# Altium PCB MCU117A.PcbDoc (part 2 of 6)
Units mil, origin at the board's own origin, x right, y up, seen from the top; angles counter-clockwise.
Board outline 2300 x 6749.64 mil, 6 copper layers (Top Signal, GND, Middle Signal, PWR, GND2, Bottom Signal), stack 61.64 mil thick; 424 components, 343 nets, 1563 pads, 921 vias.
Unrouted connection lines stored in the file: 4.
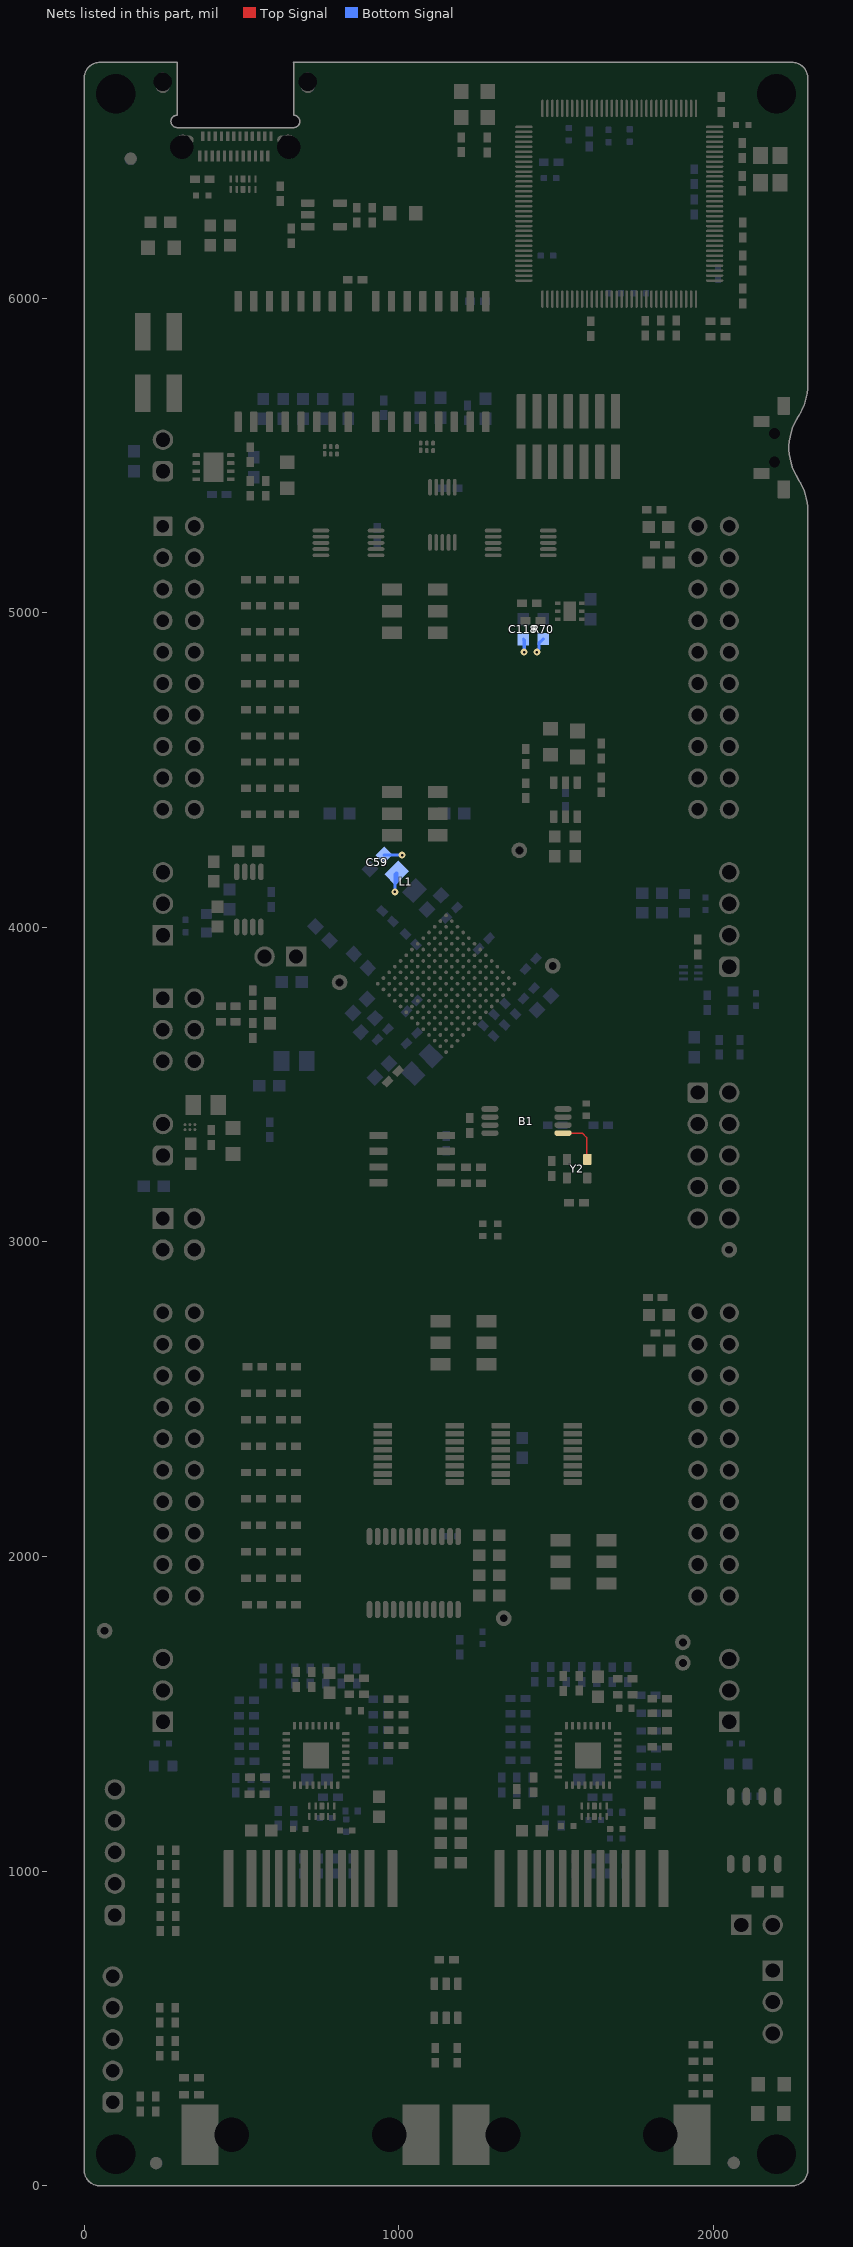
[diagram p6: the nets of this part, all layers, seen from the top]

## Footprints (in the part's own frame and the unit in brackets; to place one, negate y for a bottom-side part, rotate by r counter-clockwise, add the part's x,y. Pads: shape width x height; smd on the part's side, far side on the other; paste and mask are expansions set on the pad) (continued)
DW0016B_HV [mm] "SOIC-16, HV/isolation option"
  rrect17% 1.65x0.6 smd: 1(-4.875,4.445) 2(-4.875,3.175) 3(-4.875,1.905) 4(-4.875,0.635) 5(-4.875,-0.635) 6(-4.875,-1.905) 7(-4.875,-3.175) 8(-4.875,-4.445) 9(4.875,-4.445) 10(4.875,-3.175) 11(4.875,-1.905) 12(4.875,-0.635) 13(4.875,0.635) 14(4.875,1.905) 15(4.875,3.175) 16(4.875,4.445)
  body extent -5.17,-5.15 5.17,5.15, height 2.59
EtherCAT_label [mil] "ETHERCAT_LABEL"
FCC_disclaimer [mil]
Fiducial10-20 [mm]
  round 1 smd mask+0.5: 1(0,0)
  Top Signal keep-out circle w1.178: c0,0 r0.5
FP-61300421121_HDR4-MFG [mm]
  rrect6% 1.7x1.7 hole 1.1: 1(-1.27,-1.27)
  round 1.7 hole 1.1: 2(-1.27,1.27) 3(1.27,-1.27) 4(1.27,1.27)
  silkscreen extent -2.69,-3.22 2.69,2.62, body extent -2.79,-2.72 2.79,2.72, height 0.25
FP-885012005053_0402-MFG [mm]
  rrect20% 0.5x0.5 smd paste+0 mask+0: 1(-0.5,0) 2(0.5,0)
  silkscreen extent -0.53,-0.63 0.53,0.63, body extent -0.5,-0.25 0.5,0.25, height 0.55
FP-885012205018_0402-MFG [mm]
  rrect20% 0.5x0.5 smd paste+0 mask+0: 1(-0.5,0) 2(0.5,0)
  silkscreen extent -0.5,-0.63 0.5,0.63, body extent -0.5,-0.25 0.5,0.25, height 0.55
FP-885012205050_0402-MFG [mm]
  rrect20% 0.5x0.5 smd paste+0 mask+0: 1(-0.5,0) 2(0.5,0)
  silkscreen extent -0.53,-0.63 0.53,0.63, body extent -0.85,-0.38 0.85,0.38, height 0.25
FP-885012205064_0402-MFG [mm]
  rrect20% 0.5x0.5 smd paste+0 mask+0: 1(-0.5,0) 2(0.5,0)
  silkscreen extent -0.53,-0.63 0.53,0.63, body extent -0.85,-0.38 0.85,0.38, height 0.25
FP-CC0603KRX5R6BB106_0603-MFG [mm]
  rrect13% 0.8x0.9 smd paste+0 mask+0: 1(-0.75,0) 2(0.75,0)
  silkscreen extent -0.85,-0.87 0.85,0.87, body extent -0.8,-0.4 0.8,0.4, height 1
FP-FTSH-107-01-F-DV-K_HDR14-MFG [mm]
  rrect14% 0.74x2.79 smd paste+0 mask+0: 1(-3.81,-2.035) 2(-3.81,2.035) 3(-2.54,-2.035) 4(-2.54,2.035) 5(-1.27,-2.035) 6(-1.27,2.035) 7(0,-2.035) 8(0,2.035) 9(1.27,-2.035) 10(1.27,2.035) 11(2.54,-2.035) 12(2.54,2.035) 13(3.81,-2.035) 14(3.81,2.035)
  silkscreen extent -4.51,-4.11 4.51,0.27, body extent -4.61,-3.53 4.61,3.53, height 0.25
FP-MUP-U22001_CONN_USB_8MM94_8MM0-MFG [mm]
  rrect100% 0.6x1.9 hole 1.9 slot 0.6 at 0 deg: 1(-4.32,3.35) 2(4.32,3.35)
  round 1.207 smd: 1(-4.25,2.92) 2(4.25,2.92)
  round 1.207 smd far side: 1(-4.25,2.92) 2(4.25,2.92)
  rrect100% 1.25x0.7 hole 0.7 slot 1.25 at 0 deg: 1(-3.995,2.75) 2(3.995,2.75)
  rrect100% 0.7x1.5 hole 1.5 slot 0.7 at 0 deg: 3(-5.85,-1.95) 4(5.85,-1.95)
  round 1.17 smd far side: 3(-5.85,-1.625) 4(5.85,-1.625)
  round 1.17 smd: 3(-5.85,-1.625) 4(5.85,-1.625)
  rrect37% 0.27x0.9 smd: A1(-2.625,4.05) A2(-2.125,4.05) A3(-1.625,4.05) A4(-1.125,4.05) A5(-0.625,4.05) A6(-0.125,4.05) A7(0.375,4.05) A8(0.875,4.05) A9(1.375,4.05) A10(1.875,4.05) A11(2.375,4.05) A12(2.875,4.05)
  rrect37% 0.27x0.8 smd: B1(2.625,2.45) B2(2.125,2.45) B3(1.625,2.45) B4(1.125,2.45) B5(0.625,2.45) B6(0.125,2.45) B7(-0.375,2.45) B8(-0.875,2.45) B9(-1.375,2.45) B10(-1.875,2.45) B11(-2.375,2.45) B12(-2.875,2.45)
  Top Signal region: -6.5,-2.349 -6.5,-2.472 -6.411,-2.701 -6.244,-2.882 -6.023,-2.99 -5.9,-2.999 -5.9,-2.999 -5.833,-3.004 -5.699,-2.987 -5.572,-2.942 -5.457,-2.873 -5.358,-2.781 -5.281,-2.672 -5.227,-2.548 -5.2,-2.416 -5.2,-2.349 -5.2,-2.349 -5.2,-0.749 -5.2,-0.65 -5.276,-0.466 -5.417,-0.325 -5.601,-0.249 -5.7,-0.249 -5.7,-0.249 -6,-0.249 -6.099,-0.249 -6.283,-0.325 -6.424,-0.466 -6.5,-0.65 -6.5,-0.749 -6.5,-0.749
  Top Signal region: 6.5,-2.349 6.5,-2.472 6.411,-2.701 6.244,-2.882 6.023,-2.99 5.9,-2.999 5.833,-3.004 5.699,-2.987 5.572,-2.942 5.457,-2.873 5.358,-2.781 5.281,-2.672 5.227,-2.548 5.2,-2.416 5.2,-2.349 5.2,-2.349 5.2,-0.749 5.2,-0.65 5.276,-0.466 5.417,-0.325 5.601,-0.249 5.7,-0.249 5.7,-0.249 6,-0.249 6.099,-0.249 6.283,-0.325 6.424,-0.466 6.5,-0.65 6.5,-0.749 6.5,-0.749
  Top Signal region: -3.72,3.35 -3.72,4.05 -3.72,4.169 -3.811,4.39 -3.98,4.559 -4.201,4.65 -4.32,4.65 -4.439,4.65 -4.66,4.559 -4.829,4.39 -4.92,4.169 -4.92,4.05 -4.92,4.05 -4.92,2.85 -4.92,2.731 -4.829,2.51 -4.66,2.341 -4.439,2.25 -4.32,2.25 -4.32,2.25 -3.82,2.25 -3.711,2.25 -3.508,2.334 -3.354,2.488 -3.27,2.691 -3.27,2.8 -3.268,2.898 -3.332,3.082 -3.456,3.233 -3.624,3.332 -3.72,3.35
  Top Signal region: 3.72,3.35 3.72,4.05 3.72,4.169 3.811,4.39 3.98,4.559 4.201,4.65 4.32,4.65 4.439,4.65 4.66,4.559 4.829,4.39 4.92,4.169 4.92,4.05 4.92,4.05 4.92,2.85 4.92,2.731 4.829,2.51 4.66,2.341 4.439,2.25 4.32,2.25 4.32,2.25 3.82,2.25 3.711,2.25 3.508,2.334 3.354,2.488 3.27,2.691 3.27,2.8 3.268,2.898 3.332,3.082 3.456,3.233 3.624,3.332 3.72,3.35 3.72,3.35
  Bottom Signal region: -6.5,-2.349 -6.5,-2.472 -6.411,-2.701 -6.244,-2.882 -6.023,-2.99 -5.9,-2.999 -5.833,-3.004 -5.699,-2.987 -5.572,-2.942 -5.457,-2.873 -5.358,-2.781 -5.281,-2.672 -5.227,-2.548 -5.2,-2.416 -5.2,-2.349 -5.2,-2.349 -5.2,-0.749 -5.2,-0.65 -5.276,-0.466 -5.417,-0.325 -5.601,-0.249 -5.7,-0.249 -5.7,-0.249 -6,-0.249 -6.099,-0.249 -6.283,-0.325 -6.424,-0.466 -6.5,-0.65 -6.5,-0.749 -6.5,-0.749
  Bottom Signal region: 6.5,-2.349 6.5,-2.472 6.411,-2.701 6.244,-2.882 6.023,-2.99 5.9,-2.999 5.833,-3.004 5.699,-2.987 5.572,-2.942 5.457,-2.873 5.358,-2.781 5.281,-2.672 5.227,-2.548 5.2,-2.416 5.2,-2.349 5.2,-2.349 5.2,-0.749 5.2,-0.65 5.276,-0.466 5.417,-0.325 5.601,-0.249 5.7,-0.249 5.7,-0.249 6,-0.249 6.099,-0.249 6.283,-0.325 6.424,-0.466 6.5,-0.65 6.5,-0.749 6.5,-0.749
  Bottom Signal region: -3.72,3.35 -3.72,4.05 -3.72,4.169 -3.811,4.39 -3.98,4.559 -4.201,4.65 -4.32,4.65 -4.439,4.65 -4.66,4.559 -4.829,4.39 -4.92,4.169 -4.92,4.05 -4.92,4.05 -4.92,2.85 -4.92,2.731 -4.829,2.51 -4.66,2.341 -4.439,2.25 -4.32,2.25 -4.32,2.25 -3.82,2.25 -3.711,2.25 -3.508,2.334 -3.354,2.488 -3.27,2.691 -3.27,2.8 -3.268,2.898 -3.332,3.082 -3.456,3.233 -3.624,3.332 -3.72,3.35
  Bottom Signal region: 3.72,3.35 3.72,4.05 3.72,4.169 3.811,4.39 3.98,4.559 4.201,4.65 4.32,4.65 4.439,4.65 4.66,4.559 4.829,4.39 4.92,4.169 4.92,4.05 4.92,4.05 4.92,2.85 4.92,2.731 4.829,2.51 4.66,2.341 4.439,2.25 4.32,2.25 4.32,2.25 3.82,2.25 3.711,2.25 3.508,2.334 3.354,2.488 3.27,2.691 3.27,2.8 3.268,2.898 3.332,3.082 3.456,3.233 3.624,3.332 3.72,3.35
  Keep-Out Layer lines w0.2: 4.7,-3.5 4.7,0.75 ccw(c4.7,1.25) 5.2,1.25 ccw(c4.7,1.25) 4.7,1.75 -4.7,1.75 ccw(c-4.7,1.25) -5.2,1.25 ccw(c-4.7,1.25) -4.7,0.75 -4.7,-3.5
  silkscreen extent -6,0.13 6,5.17, body extent -6.6,-4.23 6.6,4.75, height 0.25
"FP-RMCF0402ZT0R00_0402 (1005 metric)-0" [mm]
  rrect20% 0.5x0.6 smd paste+0 mask+0: 1(-0.5,0) 2(0.5,0)
  body extent -0.5,-0.25 0.5,0.25, height 0.35
LED_LTST-C171 [mm] "LITE-ON"
  rect 1.2x1.2 smd: 1(-1.05,0) 2(1.05,0)
  silkscreen extent -1.6,-1 2.2,1, body extent -1.05,-0.67 1.05,0.67, height 0.8
LTST-C170TBKT_Blue [mm] "LITE-ON"
  rect 1.2x1.2 smd: 1(-1.05,0) 2(1.05,0)
  silkscreen extent -1.6,-1 2.2,1, body extent -1.05,-0.67 1.05,0.67, height 1.2
NDK_NX3225GA [mm] "NDK"
  rect 1.2x1.4 smd: 1(-0.8,1.1) 2(-0.8,-1.1) 3(0.8,-1.1) 4(0.8,1.1)
  silkscreen extent -1.9,-0.1 1.4,2, body extent -1.3,-1.65 1.3,1.65, height 0.9
NMR0169A-MFG [mm]
  round 0.3 smd paste+0 mask+0: A1(-3.9,3.9) A2(-3.25,3.9) A3(-2.6,3.9) A4(-1.95,3.9) A5(-1.3,3.9) A6(-0.65,3.9) A7(0,3.9) A8(0.65,3.9) A9(1.3,3.9) A10(1.95,3.9) A11(2.6,3.9) A12(3.25,3.9) A13(3.9,3.9) B1(-3.9,3.25) B2(-3.25,3.25) B3(-2.6,3.25) B4(-1.95,3.25) B5(-1.3,3.25) B6(-0.65,3.25) B7(0,3.25) B8(0.65,3.25) B9(1.3,3.25) B10(1.95,3.25) B11(2.6,3.25) B12(3.25,3.25) B13(3.9,3.25) C1(-3.9,2.6) C2(-3.25,2.6) C3(-2.6,2.6) C4(-1.95,2.6) C5(-1.3,2.6) C6(-0.65,2.6) C7(0,2.6) C8(0.65,2.6) C9(1.3,2.6) C10(1.95,2.6) C11(2.6,2.6) C12(3.25,2.6) C13(3.9,2.6) D1(-3.9,1.95) D2(-3.25,1.95) D3(-2.6,1.95) D4(-1.95,1.95) D5(-1.3,1.95) D6(-0.65,1.95) D7(0,1.95) D8(0.65,1.95) D9(1.3,1.95) D10(1.95,1.95) D11(2.6,1.95) D12(3.25,1.95) D13(3.9,1.95) E1(-3.9,1.3) E2(-3.25,1.3) E3(-2.6,1.3) E4(-1.95,1.3) E5(-1.3,1.3) E6(-0.65,1.3) E7(0,1.3) E8(0.65,1.3) E9(1.3,1.3) E10(1.95,1.3) E11(2.6,1.3) E12(3.25,1.3) E13(3.9,1.3) F1(-3.9,0.65) F2(-3.25,0.65) F3(-2.6,0.65) F4(-1.95,0.65) F5(-1.3,0.65) F6(-0.65,0.65) F7(0,0.65) F8(0.65,0.65) F9(1.3,0.65) F10(1.95,0.65) F11(2.6,0.65) F12(3.25,0.65) F13(3.9,0.65) G1(-3.9,0) G2(-3.25,0) G3(-2.6,0) G4(-1.95,0) G5(-1.3,0) G6(-0.65,0) G7(0,0) G8(0.65,0) G9(1.3,0) G10(1.95,0) G11(2.6,0) G12(3.25,0) G13(3.9,0) H1(-3.9,-0.65) H2(-3.25,-0.65) H3(-2.6,-0.65) H4(-1.95,-0.65) H5(-1.3,-0.65) H6(-0.65,-0.65) H7(0,-0.65) H8(0.65,-0.65) H9(1.3,-0.65) H10(1.95,-0.65) H11(2.6,-0.65) H12(3.25,-0.65) H13(3.9,-0.65) J1(-3.9,-1.3) J2(-3.25,-1.3) J3(-2.6,-1.3) J4(-1.95,-1.3) J5(-1.3,-1.3) J6(-0.65,-1.3) J7(0,-1.3) J8(0.65,-1.3) J9(1.3,-1.3) J10(1.95,-1.3) J11(2.6,-1.3) J12(3.25,-1.3) J13(3.9,-1.3) K1(-3.9,-1.95) K2(-3.25,-1.95) K3(-2.6,-1.95) K4(-1.95,-1.95) K5(-1.3,-1.95) K6(-0.65,-1.95) K7(0,-1.95) K8(0.65,-1.95) K9(1.3,-1.95) K10(1.95,-1.95) K11(2.6,-1.95) K12(3.25,-1.95) K13(3.9,-1.95) L1(-3.9,-2.6) L2(-3.25,-2.6) L3(-2.6,-2.6) L4(-1.95,-2.6) L5(-1.3,-2.6) L6(-0.65,-2.6) L7(0,-2.6) L8(0.65,-2.6) L9(1.3,-2.6) L10(1.95,-2.6) L11(2.6,-2.6) L12(3.25,-2.6) L13(3.9,-2.6) M1(-3.9,-3.25) M2(-3.25,-3.25) M3(-2.6,-3.25) M4(-1.95,-3.25) M5(-1.3,-3.25) M6(-0.65,-3.25) M7(0,-3.25) M8(0.65,-3.25) M9(1.3,-3.25) M10(1.95,-3.25) M11(2.6,-3.25) M12(3.25,-3.25) M13(3.9,-3.25) N1(-3.9,-3.9) N2(-3.25,-3.9) N3(-2.6,-3.9) N4(-1.95,-3.9) N5(-1.3,-3.9) N6(-0.65,-3.9) N7(0,-3.9) N8(0.65,-3.9) N9(1.3,-3.9) N10(1.95,-3.9) N11(2.6,-3.9) N12(3.25,-3.9) N13(3.9,-3.9)
  silkscreen extent -5.15,-4.55 4.55,4.55, body extent -4.5,-4.5 4.5,4.5, height 1
NPTH125mil#1 [mil]
  round 120 hole 125 unplated: 1(0,0)
NPTH125mil#2 [mil]
  round 120 hole 125 unplated: 1(0,-1249.64)
PDT0128A [mm] "Thin QFP, 128-Leads, Body 14x14mm, Pitch 0.4mm"
  oval 1.4x0.2 smd: 1(-7.7,6.2) 2(-7.7,5.8) 3(-7.7,5.4) 4(-7.7,5) 5(-7.7,4.6) 6(-7.7,4.2) 7(-7.7,3.8) 8(-7.7,3.4) 9(-7.7,3) 10(-7.7,2.6) 11(-7.7,2.2) 12(-7.7,1.8) 13(-7.7,1.4) 14(-7.7,1) 15(-7.7,0.6) 16(-7.7,0.2) 17(-7.7,-0.2) 18(-7.7,-0.6) 19(-7.7,-1) 20(-7.7,-1.4) 21(-7.7,-1.8) 22(-7.7,-2.2) 23(-7.7,-2.6) 24(-7.7,-3) 25(-7.7,-3.4) 26(-7.7,-3.8) 27(-7.7,-4.2) 28(-7.7,-4.6) 29(-7.7,-5) 30(-7.7,-5.4) 31(-7.7,-5.8) 32(-7.7,-6.2) 65(7.7,-6.2) 66(7.7,-5.8) 67(7.7,-5.4) 68(7.7,-5) 69(7.7,-4.6) 70(7.7,-4.2) 71(7.7,-3.8) 72(7.7,-3.4) 73(7.7,-3) 74(7.7,-2.6) 75(7.7,-2.2) 76(7.7,-1.8) 77(7.7,-1.4) 78(7.7,-1) 79(7.7,-0.6) 80(7.7,-0.2) 81(7.7,0.2) 82(7.7,0.6) 83(7.7,1) 84(7.7,1.4) 85(7.7,1.8) 86(7.7,2.2) 87(7.7,2.6) 88(7.7,3) 89(7.7,3.4) 90(7.7,3.8) 91(7.7,4.2) 92(7.7,4.6) 93(7.7,5) 94(7.7,5.4) 95(7.7,5.8) 96(7.7,6.2)
  oval 0.2x1.4 smd: 33(-6.2,-7.7) 34(-5.8,-7.7) 35(-5.4,-7.7) 36(-5,-7.7) 37(-4.6,-7.7) 38(-4.2,-7.7) 39(-3.8,-7.7) 40(-3.4,-7.7) 41(-3,-7.7) 42(-2.6,-7.7) 43(-2.2,-7.7) 44(-1.8,-7.7) 45(-1.4,-7.7) 46(-1,-7.7) 47(-0.6,-7.7) 48(-0.2,-7.7) 49(0.2,-7.7) 50(0.6,-7.7) 51(1,-7.7) 52(1.4,-7.7) 53(1.8,-7.7) 54(2.2,-7.7) 55(2.6,-7.7) 56(3,-7.7) 57(3.4,-7.7) 58(3.8,-7.7) 59(4.2,-7.7) 60(4.6,-7.7) 61(5,-7.7) 62(5.4,-7.7) 63(5.8,-7.7) 64(6.2,-7.7) 97(6.2,7.7) 98(5.8,7.7) 99(5.4,7.7) 100(5,7.7) 101(4.6,7.7) 102(4.2,7.7) 103(3.8,7.7) 104(3.4,7.7) 105(3,7.7) 106(2.6,7.7) 107(2.2,7.7) 108(1.8,7.7) 109(1.4,7.7) 110(1,7.7) 111(0.6,7.7) 112(0.2,7.7) 113(-0.2,7.7) 114(-0.6,7.7) 115(-1,7.7) 116(-1.4,7.7) 117(-1.8,7.7) 118(-2.2,7.7) 119(-2.6,7.7) 120(-3,7.7) 121(-3.4,7.7) 122(-3.8,7.7) 123(-4.2,7.7) 124(-4.6,7.7) 125(-5,7.7) 126(-5.4,7.7) 127(-5.8,7.7) 128(-6.2,7.7)
  silkscreen extent -7.7,-6.3 6.3,6.99, body extent -8,-8 8,8, height 1.07
PW0008A_N [mm] "TSOP, 8-Leads, Body 3x4.4mm, Pitch 0.65mm, IPC Medium Density"
  oval 1.4x0.45 smd: 1(-2.95,0.975) 2(-2.95,0.325) 3(-2.95,-0.325) 4(-2.95,-0.975) 5(2.95,-0.975) 6(2.95,-0.325) 7(2.95,0.325) 8(2.95,0.975)
  silkscreen extent -3.4,-1.55 1.85,1.55, body extent -3.21,-1.5 3.21,1.5, height 1.2
PW0016A-MFG [mm]
  rrect22% 1.5x0.45 smd: 1(-2.9,2.275) 2(-2.9,1.625) 3(-2.9,0.975) 4(-2.9,0.325) 5(-2.9,-0.325) 6(-2.9,-0.975) 7(-2.9,-1.625) 8(-2.9,-2.275) 9(2.9,-2.275) 10(2.9,-1.625) 11(2.9,-0.975) 12(2.9,-0.325) 13(2.9,0.325) 14(2.9,0.975) 15(2.9,1.625) 16(2.9,2.275)
  silkscreen extent -4.38,-2.55 1.78,2.55, body extent -3.75,-2.8 3.75,2.8, height 0.25
PW0024A_N [mm] "TSOP, 24-Leads, Body 7.8x4.4mm, Pitch 0.65mm, IPC Medium Density"
  oval 1.4x0.45 smd: 1(-2.95,3.575) 2(-2.95,2.925) 3(-2.95,2.275) 4(-2.95,1.625) 5(-2.95,0.975) 6(-2.95,0.325) 7(-2.95,-0.325) 8(-2.95,-0.975) 9(-2.95,-1.625) 10(-2.95,-2.275) 11(-2.95,-2.925) 12(-2.95,-3.575) 13(2.95,-3.575) 14(2.95,-2.925) 15(2.95,-2.275) 16(2.95,-1.625) 17(2.95,-0.975) 18(2.95,-0.325) 19(2.95,0.325) 20(2.95,0.975) 21(2.95,1.625) 22(2.95,2.275) 23(2.95,2.925) 24(2.95,3.575)
  silkscreen extent -3.51,-3.95 1.6,4.04, body extent -3.21,-3.9 3.21,3.9, height 1
RHB0032M [mm] "QFN, 32-Leads, Body 5x5mm, Pitch 0.5mm, Thermal Pad 2.1x2.1mm"
  rrect40% 0.6x0.25 smd: 1(-2.4,1.75) 2(-2.4,1.25) 3(-2.4,0.75) 4(-2.4,0.25) 5(-2.4,-0.25) 6(-2.4,-0.75) 7(-2.4,-1.25) 8(-2.4,-1.75) 17(2.4,-1.75) 18(2.4,-1.25) 19(2.4,-0.75) 20(2.4,-0.25) 21(2.4,0.25) 22(2.4,0.75) 23(2.4,1.25) 24(2.4,1.75)
  rrect40% 0.25x0.6 smd: 9(-1.75,-2.4) 10(-1.25,-2.4) 11(-0.75,-2.4) 12(-0.25,-2.4) 13(0.25,-2.4) 14(0.75,-2.4) 15(1.25,-2.4) 16(1.75,-2.4) 25(1.75,2.4) 26(1.25,2.4) 27(0.75,2.4) 28(0.25,2.4) 29(-0.25,2.4) 30(-0.75,2.4) 31(-1.25,2.4) 32(-1.75,2.4)
  rrect11% 0.94x0.94 on Top Paste: 33(-0.57,-0.57) 33(-0.57,0.57) 33(0.57,-0.57) 33(0.57,0.57)
  rrect5% 2.1x2.1 smd paste-1.725: 33(0,0)
  silkscreen extent -2.72,-2.73 2.72,2.72, body extent -2.55,-2.55 2.55,2.55, height 1.01
Samtec_TSM-102-01-x-DV [mil] "Header, 2.54mm, 2x2, SMT"
  rect 120x50 smd: 1(-97.44,-50) 2(97.44,-50) 3(-97.44,50) 4(97.44,50)
  silkscreen extent -69,-104 65,100, body extent -151,-100 152,100, height 380
SOIC-8 [mm] "duplicate of SO-8.  SOIC, 8-Leads, Body 5.0x4.0mm (max), Pitch 1.27mm, IPC Medium Density"
  rrect17% 1.45x0.6 smd: 1(-2.725,1.905) 2(-2.725,0.635) 3(-2.725,-0.635) 4(-2.725,-1.905) 5(2.725,-1.905) 6(2.725,-0.635) 7(2.725,0.635) 8(2.725,1.905)
  silkscreen extent -3.5,-2.5 0.9,2.5, body extent -3,-2.45 3,2.45, height 1.63
SW_1188E [mm] "SMD, 4-Leads, Body 7.8x3.5mm"
  rrect10% 1x1.45 smd: 1(-1.1,3.375) 2(-1.1,-3.375)
  rrect11% 1.3x0.9 smd: 3(0.7,2.1) 4(0.7,-2.1)
  round 0 hole 0.9 unplated: ""(-0.35,1.15) ""(-0.35,-1.15)
  silkscreen extent -1.98,-2.28 0.95,2.28, body extent -2.55,-3.9 1.05,3.9, height 3.5
SW_CAS-220TA [mm] "COPAL ELECTRONICS"
  rect 1.6x1 smd: 1(-1.85,1.75) 2(-1.85,0) 3(-1.85,-1.75) 4(1.85,1.75) 5(1.85,0) 6(1.85,-1.75)
  silkscreen extent -2.11,-2.9 2,3.58, body extent -2.1,-2.85 2.1,2.85, height 2.51
SW_CAS-D20TA [mm] "SMD, 6-Leads, Body 5.4x3.9mm, Pitch 1.75mm"
  rect 1.6x1 smd: 1(-1.85,1.75) 2(-1.85,0) 3(-1.85,-1.75) 4(1.85,1.75) 5(1.85,0) 6(1.85,-1.75)
  silkscreen extent -1.95,-2.7 1.95,2.9, body extent -2.1,-2.7 2.1,2.7, height 2.5
TI_Stacked_Overlay_Medium [mil]
  silkscreen extent -575,-136 576,135
TI_Symbol_Overlay_Small [mil]
  silkscreen extent -90,-88 91,88
TP_50MIL-25MILHOLE#1 [mil]
  round 50 hole 25: 1(1000,91)
TP_50MIL-25MILHOLE#2 [mil]
  round 50 hole 25: 1(1156.36,0)
TP_50MIL-25MILHOLE#3 [mil]
  round 50 hole 25: 1(0,0)
WEEE_Minimum [mil] "WEEElie bin"
  silkscreen extent -95,-172 99,104
WL-SMCW_Green_0805 [mm] "SMD, 2-Leads, Body 2x1.25mm"
  rect 1.1x1.2 smd: 1(-1.05,0) 2(1.05,0)
  silkscreen extent -2.4,-1.1 1.5,1.1, body extent -1,-0.62 1,0.63, height 0.7
WL-SMCW_RED_0805 [mm] "SMD, 2-Leads, Body 1.6x0.8mm"
  rect 1.1x1.2 smd: 1(-1.05,0) 2(1.05,0)
  silkscreen extent -2.4,-1.1 1.5,1.1, body extent -1,-0.62 1,0.63, height 0.7
Wurth_7498010210A [mm] "Connector, RJ45, 1x1, Gold, R/A, SMT"
  rrect12% 4.6x0.81 smd: 1(-20.69,6.61) 2(-20.69,4.77) 11(-20.69,-4.77) 12(-20.69,-6.61)
  rrect16% 4.6x0.61 smd: 3(-20.69,3.57) 4(-20.69,2.55) 5(-20.69,1.53) 6(-20.69,0.51) 7(-20.69,-0.51) 8(-20.69,-1.53) 9(-20.69,-2.55) 10(-20.69,-3.57)
  rrect3% 4.9x3 smd: 13(0,8.92) 14(0,-8.92)
  round 2.5 hole 2.8 unplated mask+0.102: ALIGN1(0,6.35) ALIGN2(0,-6.35)
  body extent -21.42,-9.65 5.43,9.65, height 15.22
Wurth_60900213421 [mil] "Shunt, 2.54mm, Black"
  round 1 on Mech3: 0(0,0)
  body extent -98,-48 98,48, height 338
WURTH_61300211121#1 [mm] "Header, 2.54mm, 2x1, TH"
  rect 1.65x1.65 hole 1.15: 1(-1.27,0)
  round 1.65 hole 1.15: 2(1.27,0)
  silkscreen extent -2.54,-1.27 2.54,1.6, body extent -2.54,-1.27 2.54,1.27, height 8.54
WURTH_61300211121#2 [mm] "Header, 2.54mm, 2x1, TH"
  rrect50% 1.65x1.65 hole 1.15: 1(-1.27,0)
  round 1.65 hole 1.15: 2(1.27,0)
  body extent -2.54,-1.27 2.54,1.27, height 8.54
WURTH_61300311121 [mm] "Header, 2.54mm, 3x1, TH"
  rect 1.65x1.65 hole 1.15: 1(-2.54,0)
  round 1.65 hole 1.15: 2(0,0) 3(2.54,0)
  silkscreen extent -3.81,-1.7 3.81,1.27, body extent -3.81,-1.27 3.81,1.27, height 8.54
WURTH_61300411121 [mm] "Header, 2.54mm, 4x1, TH"
  rrect50% 1.65x1.65 hole 1.15: 1(-3.81,0)
  round 1.65 hole 1.15: 2(-1.27,0) 3(1.27,0) 4(3.81,0)
  body extent -5.08,-1.27 5.08,1.27, height 8.54
Wurth_61300511121 [mm] "Header, 2.54mm, 5x1, TH"
  rrect50% 1.65x1.65 hole 1.1: 1(-5.08,0)
  round 1.65 hole 1.1: 2(-2.54,0) 3(0,0) 4(2.54,0) 5(5.08,0)
  body extent -6.35,-1.27 6.35,1.27, height 8.54
Wurth_61300621121 [mm] "Header, 2.54mm, 3x2, TH"
  rect 1.6x1.6 hole 1.1: 1(-1.27,2.54)
  round 1.6 hole 1.1: 2(1.27,2.54) 3(-1.27,0) 4(1.27,0) 5(-1.27,-2.54) 6(1.27,-2.54)
  silkscreen extent -2.8,-3.82 2.54,3.8, body extent -2.54,-3.82 2.54,3.8, height 7.27
WURTH_61301021121 [mm] "Header, 2.54mm, 5x2, TH"
  rrect25% 1.65x1.65 hole 1.15: 1(-5.08,-1.27)
  round 1.65 hole 1.15: 2(-5.08,1.27) 3(-2.54,-1.27) 4(-2.54,1.27) 5(0,-1.27) 6(0,1.27) 7(2.54,-1.27) 8(2.54,1.27) 9(5.08,-1.27) 10(5.08,1.27)
  silkscreen extent -6.35,-2.9 6.35,2.54, body extent -6.35,-2.54 6.35,2.54, height 8.54
YFF0006AEAE [mm] "DSBGA-6"
  round 0.23 smd paste-0.13 mask+0.038: A1(-0.2,0.4) A2(0.2,0.4) B1(-0.2,0) B2(0.2,0) C1(-0.2,-0.4) C2(0.2,-0.4)
  body extent -0.45,-0.65 0.45,0.65, height 0.63

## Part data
B1: library part CMP-0860874-2, "3.3-V and 2.5-V LVCMOS High-Performance Clock Buffer Family, PW0008A (TSSOP-8)", Alternate Manufacturer="Texas Instruments", Alternate PartNumber=LMK1C1104PWR
C1 C2 C3 C4 C5 C12 C16 C17 C18 C19 C20 C28 C51 C55 C56 C57 C58 C66 C67 C68 C69 C70 C71 C72 C73 C86 C90 C98 C100 C103 C106 C114 C116 C124 C125 C128 C129 C130 C132 C133: library part CMP-0006228-2, "CAP, CERM, 0.1 uF, 16 V, +/- 10%, X7R, 0402", Cap_Case=0402, Manufacturer="Wurth Elektronik", Supplier Part Number 1=732-7532-1-ND, TempCo=X7R, Tolerance_%=10%, Value1=Unknown, Value2=16V, ValueDisplayed=0.1uF
C6 C7 C8 C9 C10 C11 C23: library part CMP-0006231-2, "CAP, CERM, 1000 pF, 50 V, +/- 10%, X7R, 0402", Cap_Case=0402, Manufacturer="Wurth Elektronik", Supplier Part Number 1=732-7556-1-ND, TempCo=X7R, Tolerance_%=10%, Value1=Unknown, Value2=50V, ValueDisplayed=1000pF
C13 C14 C15 C53: library part CMP-0007341-4, "CAP, CERM, 4.7 uF, 16 V, +/- 10%, X5R, 0603", Cap_Case=0603, Manufacturer=MuRata, Supplier Part Number 1=490-10481-1-ND, TempCo=X5R, Tolerance_%=10%, Value1=Unknown, Value2=16V, ValueDisplayed=4.7uF
C21 C22 C137 C138 C143 C145: library part CMP-0090362-1, "0.1µF ±10% 10V Ceramic Capacitor X7R 0402 (1005 Metric)", Digikey Part Number=732-7513-1-ND, Manufacturer="Wurth Electronics", Mouser Part Number=710-885012205018, Operating Temperature Range="-55°C to +125°C", TempCo=15%, Temperature Characteristic=X7R, Tolerance_%=10%, ValueDisplayed=100000pF
C24 C25: library part CMP-0006920-4, "CAP, CERM, 330 pF, 50 V, +/- 5%, C0G/NP0, 0603", Cap_Case=0603, Manufacturer=Kemet, Supplier Part Number 1=399-1068-1-ND, TempCo=C0G/NP0, Tolerance_%=5%, Value1=Unknown, Value2=50V, ValueDisplayed=330pF
C26 C27 C29 C30 C31 C32 C33 C34 C35 C36 C37 C38 C39 C40 C41 C42 C43 C44 C45 C46 C47 C48 C49 C50: library part CMP-0006456-2, "CAP, CERM, 330 pF, 50 V, +/- 5%, C0G/NP0, 0402", Cap_Case=0402, Manufacturer=MuRata, Supplier Part Number 1=490-1295-1-ND, TempCo=C0G/NP0, Tolerance_%=5%, Value1=Unknown, Value2=50V, ValueDisplayed=330pF
C52 C97 C113: library part CMP-0007324-5, "CAP, CERM, 22 uF, 10 V, +/- 20%, X5R, 0603", Cap_Case=0603, Manufacturer=MuRata, Supplier Part Number 1=490-10476-1-ND, TempCo=X5R, Tolerance_%=20%, Value1=Unknown, Value2=10V, ValueDisplayed=22uF
C54 C59 C118 C120 C121 C122: library part CMP-0086225-1, "CAP, CERM, 10 µF, 16 V,+/- 10%, X5R, 0603", Cap_Case=0603, Manufacturer=MuRata, Supplier Part Number 1=490-10728-1-ND, TempCo=X5R, Tolerance_%=10%, Value2=16V, ValueDisplayed=10µF
C60 C61 C62 C64 C65 C85 C119: library part CMP-0006825-5, "CAP, CERM, 2.2 uF, 16 V, +/- 20%, X5R, 0603", Cap_Case=0603, Manufacturer="Wurth Elektronik", Supplier Part Number 1=732-7915-1-ND, TempCo=X5R, Tolerance_%=20%, Value1=Unknown, Value2=16V, ValueDisplayed=2.2uF
C74 C76 C78 C81 C83: library part CMP-0092309-1, "Cap Ceramic 10uF 10V X5R 10% SMD 0603 85C Paper T/R", Digikey Part Number=311-1782-1-ND, Manufacturer=YAGEO, Mouser Part Number=603-CC603KRX5R6BB106, Octopart Part Number=1f0ad7d7c223c0cd, Operating Temperature Range="-55°C to +85°C", TempCo=15%, Temperature Characteristic=X5R, Tolerance_%=10%, ValueDisplayed=10uF
C75 C77 C79 C82 C84: library part CMP-0090362-1, "0.1µF ±10% 10V Ceramic Capacitor X7R 0402 (1005 Metric)", Digikey Part Number=732-7513-1-ND, Manufacturer="Wurth Electronics", Mouser Part Number=710-885012205018, Operating Temperature Range="-55°C to +125°C", TempCo=15%, Temperature Characteristic=X7R, Tolerance_%=10%, ValueDisplayed=0.1uF
C80: library part CMP-0092424-1, "Cap Cer 3300pF 50V X7R 0402", Digikey Part Number=732-7559-1-ND, Manufacturer="Wurth Electronics", Mouser Part Number=710-885012205064, Operating Temperature Range="-55°C to +125°C", TempCo=15%, Temperature Characteristic=X7R, Tolerance_%=10%, ValueDisplayed=3.3nF
C87 C95 C102 C111: library part CMP-0006325-2, "CAP, CERM, 0.1 uF, 50 V, +/- 10%, X7R, AEC-Q200 Grade 1, 0402", Cap_Case=0402, Manufacturer=TDK, Supplier Part Number 1=445-6899-1-ND, TempCo=X7R, Tolerance_%=10%, Value1="0.039064 ohm", Value2=50V, ValueDisplayed=0.1uF
C88 C96 C104 C112: library part CMP-0086061-1, "CAP, CERM, 1 µF, 25 V,+/- 10%, X5R, 0402", Cap_Case=0402, Manufacturer=MuRata, TempCo=X5R, Tolerance_%=10%, Value2=25V, ValueDisplayed=1µF
C89 C105: library part CMP-0006283-2, "CAP, CERM, 2.2 uF, 35 V, +/- 10%, X5R, 0402", Cap_Case=0402_065, Manufacturer=TDK, Supplier Part Number 1=445-9028-1-ND, TempCo=X5R, Tolerance_%=10%, Value1="0.005925 ohm", Value2=35V, ValueDisplayed=2.2uF
C91 C92 C93 C94 C107 C108 C109 C110: library part CMP-0096999-1, "4.7 pF ±0.5pF 50V Ceramic Capacitor C0G, NP0 0402 (1005 Metric)", Digikey Part Number=732-7467-1-ND, Manufacturer="Wurth Electronics", Mouser Part Number=710-885012005053, Operating Temperature Range="-55°C to +125°C", TempCo=30ppm/°C, Temperature Characteristic=NP0, ValueDisplayed=4.7pF
C99 C115: library part CMP-0007313-5, "CAP, CERM, 47 uF, 6.3 V, +/- 20%, X5R, 0603", Cap_Case=0603, Manufacturer=MuRata, TempCo=X5R, Tolerance_%=20%, Value1=Unknown, Value2=6.3V, ValueDisplayed=47uF
C101 C117: library part CMP-0006674-2, "CAP, CERM, 0.01 uF, 50 V, +/- 10%, X7R, 0402", Cap_Case=0402, Manufacturer=MuRata, Supplier Part Number 1=490-4516-1-ND, TempCo=X7R, Tolerance_%=10%, Value1=Unknown, Value2=50V, ValueDisplayed=0.01uF
C123: library part CMP-0006560-2, "CAP, CERM, 1000 pF, 10 V, +/- 10%, X5R, 0402", Cap_Case=0402, Manufacturer=MuRata, Supplier Part Number 1=GRM155R61A102KA01D-ND, TempCo=X5R, Tolerance_%=10%, Value1=Unknown, Value2=10V, ValueDisplayed=1000pF
C126 C127: library part CMP-0078623-1, "CAP, CERM, 10 µF, 10 V,+/- 20%, X5R, 0402", Cap_Case=0402_080, Manufacturer=AVX, Supplier Part Number 1=478-10052-1-ND, TempCo=X5R, Tolerance_%=20%, Value2=10V, ValueDisplayed=10µF
C131 C134 C135 C136 C141: library part CMP-0090363-1, "10000pF ±10% 25V Ceramic Capacitor X7R 0402 (1005 Metric)", Digikey Part Number=732-7545-1-ND, Manufacturer="Wurth Electronics", Mouser Part Number=710-885012205050, Operating Temperature Range="-55°C to +125°C", TempCo=15%, Temperature Characteristic=X7R, Tolerance_%=10%, ValueDisplayed=10000pF
C139 C140 C142 C144: library part CMP-0064924-2, "CAP, CERM, 1 uF, 10 V,+/- 20%, X5R, 0402", Cap_Case=0402, Manufacturer="Wurth Elektronik", Supplier Part Number 1=732-7489-1-ND, TempCo=X5R, Tolerance_%=20%, Value1=Unknown, Value2=10V, ValueDisplayed=1uF
C146 C147: library part CMP-0006345-2, "CAP, CERM, 12 pF, 50 V, +/- 5%, C0G/NP0, 0402", Cap_Case=0402, Manufacturer="Samsung Electro-Mechanics", Supplier Part Number 1=1276-1178-1-ND, TempCo=C0G/NP0, Tolerance_%=5%, Value1=Unknown, Value2=50V, ValueDisplayed=12pF
"CE Logo1": library part CMP-0074844-1
D11 LED1 LED4 LED7: library part CMP-0002951-3, "LED, Red, SMD", Color=Red, Manufacturer="Wurth Elektronik", Power_TotalModule=72mW, Value1=0.072W, Value2=1.9V
D12 LED3 LED6: library part CMP-0002960-2, "LED, Bright Green, SMD", Color="Bright Green", Manufacturer="Wurth Elektronik", Power_TotalModule=72mW, Supplier Part Number 1=732-4986-1-ND, Value1=0.072W, Value2=2V
FID1 FID2 FID3 FID4 FID5 FID6: library part CMP-0077181-1, "Fiducial mark.  There is nothing to buy or mount.", Manufacturer=N/A
J1/J3: library part CMP-0003837-4, "Receptacle, 2.54mm, 10x2, Tin, TH", Alternate Manufacturer="Major League Electronics", Alternate PartNumber=CRD-081413-A-G, Manufacturer=Samtec, Supplier Part Number 1=SAM1204-10-ND
J4/J2: library part CMP-0078266-4, "Receptacle, 2.54mm, 10x2, Tin, TH", Alternate Manufacturer="Major League Electronics", Alternate PartNumber=CRD-081413-A-G, Manufacturer=Samtec, Supplier Part Number 1=SAM1204-10-ND
J5/J7: library part CMP-0081070-3, "Receptacle, 2.54mm, 10x2, Tin, TH", Alternate Manufacturer="Major League Electronics", Alternate PartNumber=CRD-081413-A-G, Manufacturer=Samtec, Supplier Part Number 1=SAM1204-10-ND
J8/J6: library part CMP-0081071-3, "Receptacle, 2.54mm, 10x2, Tin, TH", Alternate Manufacturer="Major League Electronics", Alternate PartNumber=CRD-081413-A-G, Manufacturer=Samtec, Supplier Part Number 1=SAM1204-10-ND
J10: library part CMP-0054802-2, "Header, 2.54mm, 3x2, Gold, TH", Color=Black, Manufacturer="Wurth Elektronik", Supplier Part Number 1=732-5295-ND
J11: library part CMP-0054806-3, "Header, 2.54 mm, 5x2, Gold, TH", Current_A=3A, Manufacturer="Wurth Elektronik", Supplier Part Number 1=732-2672-ND, Voltage_V=250V
J12 J13: library part CMP-0084909-1, "Header, 2.54mm, 5x1, Gold, TH", Color=Black, Current_A=3A, Manufacturer="Wurth Elektronik", Voltage_V=250V
J14 JP5 JP6 JP7: library part CMP-0054796-1, "Header, 2.54 mm, 3x1, Gold, TH", Manufacturer="Wurth Elektronik", Supplier Part Number 1=732-5316-ND
J15 JP9: library part CMP-0054794-1, "Header, 2.54 mm, 2x1, Gold, TH", Manufacturer="Wurth Elektronik", Supplier Part Number 1=732-5315-ND
J16 J17: library part CMP-0054794-2, "Header, 2.54 mm, 2x1, Gold, TH", Color=Black, Manufacturer="Wurth Elektronik", Supplier Part Number 1=732-5315-ND
J101: library part CMP-0092335-1, "Connector, Header, Dual Row, 14 pin, .05\" pitch/row spacing, Male, Shrouded, Keyed, IDC, SMT", Current_A=3.4A, Digikey Part Number=612-FTSH-107-01-F-DV-K-ND, Manufacturer=Samtec, Mouser Part Number=200-FTSH10701FDVK, Octopart Part Number=b9dd70752dfc661a, Operating Temperature Range="-55°C to +125°C"
JP1: library part CMP-0055559-1, "Header, 2.54mm, 2x2, Gold, SMT", Color=Black, Manufacturer=Samtec, Supplier Part Number 1=TSM-102-01-L-DV-ND, Voltage_V=475V
JP4: library part CMP-0054798-2, "Header, 2.54 mm, 4x1, Gold, TH", Color=Black, Manufacturer="Wurth Elektronik", Supplier Part Number 1=732-5317-ND
JP8: library part CMP-0092422-1, "THT Vertical Pin Header WR-PHD, Pitch 2.54 mm, Dual Row, 4 pins", Current_A=3A, Digikey Part Number=732-5294-ND, Manufacturer="Wurth Electronics", Mouser Part Number=710-61300421121, Operating Temperature Range="-40°C to +105°C", Voltage_V=250V
L1: library part CMP-0003363-1, "Ferrite Bead, 220 ohm @ 100 MHz, 2 A, 0805", Manufacturer=MuRata, Supplier Part Number 1=490-1054-1-ND, Value1="0.045 ohm", Value2=2A, ValueDisplayed="220 ohm"
L2 L3: library part CMP-0003093-1, "Ferrite Bead, 60 ohm @ 100 MHz, 3 A, 0805", Manufacturer="Wurth Elektronik", PartNumber=742792063, Supplier Part Number 1=732-1612-1-ND, Value1="0.025 ohm", Value2=3A
L4: library part CMP-0058739-1, "Inductor, Multilayer, Ferrite, 1 uH, 0.8 A, 0.19 ohm, SMD", Manufacturer=MuRata, Supplier Part Number 1=490-4992-1-ND, Value1="0.19 ohm", Value2=0.8A, ValueDisplayed=1uH
LED5: library part CMP-0002830-3, "LED, Green, SMD", Color=green, Manufacturer=Lite-On, Value1=W, Value2=2.1V
LED8 LED9: library part CMP-0002889-2, "LED, Blue, SMD", Color=Blue, Manufacturer=Lite-On, Value1=W, Value2=3.3V
Logo1 Logo5: library part CMP-0074838-1, "Texas Instrument Corporate Signature"
Logo3: library part CMP-0074847-1, "FCC_disclaimer"
Logo4: library part CMP-0074769-1
Logo6: library part CMP-0084011-3, "EtherCAT logo"
M1 M2 M3 M4 M5 M6 M7: library part CMP-0003761-2, "Shunt, 2.54mm, Gold, Black", Manufacturer="Wurth Elektronik", Supplier Part Number 1=732-2678-ND
MH1 MH2 MH3 MH4: library part CMP-0078424-2, "PCB Mounting Hole, No Pad", Manufacturer=Any, PartNumber=N/A
R1 R2 R3 R4 R25 R27 R28 R29 R47 R53 R70 R74 R76 R95 R97 R98 R99 R100 R165 R171: library part CMP-0025874-4, "RES, 0, 5%, 0.1 W, AEC-Q200 Grade 0, 0603", Manufacturer=Panasonic, Power_W=100mW, Supplier Part Number 1=P0.0GCT-ND, TempCo="600 ppm/C", Tolerance_%=5%, Value2=0.1W, Value_Code=0000, ValueDisplayed=0
R5 R6 R7 R8 R9 R10 R101 R102 R103 R104: library part CMP-0026071-3, "RES, 1.00 k, 1%, 0.063 W, AEC-Q200 Grade 0, 0402", Manufacturer=Vishay-Dale, Power_W=63mW, Supplier Part Number 1=541-1.00KLCT-ND, TempCo="100 ppm/C", Tolerance_%=1%, Value2=0.063W, Value_Code=1k00, ValueDisplayed=1.00k
R11: library part CMP-0022769-3, "RES, 120, 1%, 0.1 W, 0603", Manufacturer="Yageo America", Power_W=100mW, Supplier Part Number 1=311-120HRCT-ND, TempCo="200 ppm/C", Tolerance_%=1%, Value2=0.1W, Value_Code=120R, ValueDisplayed=120
R12 R13 R90 R96 R138: library part CMP-0026962-3, "RES, 680, 5%, 0.063 W, AEC-Q200 Grade 0, 0402", Manufacturer=Vishay-Dale, Power_W=63mW, Supplier Part Number 1=541-680JCT-ND, TempCo="200 ppm/C", Tolerance_%=5%, Value2=0.063W, Value_Code=680R, ValueDisplayed=680
R14 R15: library part CMP-0026826-2, "RES, 10 M, 5%, 0.063 W, AEC-Q200 Grade 0, 0402", Manufacturer=Vishay-Dale, Power_W=63mW, Supplier Part Number 1=541-10MJCT-ND, TempCo="200 ppm/C", Tolerance_%=5%, Value2=0.063W, Value_Code=10M0, ValueDisplayed=10M
R16: library part CMP-0026918-5, "RES, 3.3 k, 5%, 0.063 W, AEC-Q200 Grade 0, 0402", Manufacturer=Vishay-Dale, Power_W=63mW, Supplier Part Number 1=541-3.3KJCT-ND, TempCo="200 ppm/C", Tolerance_%=5%, Value2=0.063W, Value_Code=3k30, ValueDisplayed=3.3k
R17 R19 R30 R35 R36 R37: library part CMP-0025697-4, "RES, 0, 5%, 0.1 W, AEC-Q200 Grade 0, 0603", Manufacturer=Vishay-Dale, Power_W=100mW, Supplier Part Number 1=541-0.0GCT-ND, TempCo="200 ppm/C", Tolerance_%=5%, Value2=0.1W, Value_Code=0000, ValueDisplayed=0
R18 R38 R39 R40 R41 R42 R43 R45 R46 R48 R49 R50 R51 R52 R54 R55 R56 R57 R60 R61 R62 R63 R64 R65: library part CMP-0027004-2, "RES, 0, 5%, 0.063 W, 0402", Manufacturer="Yageo America", Power_W=63mW, Supplier Part Number 1=311-0.0JRCT-ND, TempCo="200 ppm/C", Tolerance_%=5%, Value2=0.063W, Value_Code=0000, ValueDisplayed=0
R20 R21 R22: library part CMP-0026765-1, "RES, 10.0, 0.1%, 0.063 W, 0402", Manufacturer="TE Connectivity", Power_W=63mW, Supplier Part Number 1=A102583CT-ND, TempCo="25 ppm/C", Tolerance_%=0.1%, Value2=0.063W, Value_Code=10R0, ValueDisplayed=10.0
R23 R24 R26 R58 R83 R84 R86 R87 R91 R92 R110 R144 R203: library part CMP-0081856-1, "RES, 0, 0%, 0.2 W, AEC-Q200 Grade 0, 0402", Manufacturer=Vishay-Dale, Power_W=200mW, Supplier Part Number 1=541-0.0YBTR-ND, Tolerance_%=0%, Value2=0.2W, Value_Code=0
R31 R33: library part CMP-0022746-5, "RES, 10.0 k, 1%, 0.1 W, 0603", Manufacturer=Yageo, Power_W=100mW, Supplier Part Number 1=311-10.0KHRCT-ND, TempCo="100 ppm/C", Tolerance_%=1%, Value2=0.1W, Value_Code=10k0, ValueDisplayed=10.0k
R32 R105 R106 R108 R141 R142: library part CMP-0026938-1, "RES, 4.7 k, 5%, 0.063 W, 0402", Manufacturer=Vishay-Dale, Power_W=63mW, Supplier Part Number 1=541-4.7KJCT-ND, TempCo="200 ppm/C", Tolerance_%=5%, Value2=0.063W, Value_Code=4k70, ValueDisplayed=4.7k
R34: library part CMP-0025769-4, "RES, 2.2 k, 5%, 0.1 W, AEC-Q200 Grade 0, 0603", Manufacturer=Vishay-Dale, Power_W=100mW, Supplier Part Number 1=541-2.2KGCT-ND, TempCo="200 ppm/C", Tolerance_%=5%, Value2=0.1W, Value_Code=2k20, ValueDisplayed=2.2k
R44 R59: library part CMP-0026890-5, "RES, 2.2 k, 5%, 0.063 W, AEC-Q200 Grade 0, 0402", Manufacturer=Vishay-Dale, Power_W=63mW, Supplier Part Number 1=541-2.2KJCT-ND, TempCo="200 ppm/C", Tolerance_%=5%, Value2=0.063W, Value_Code=2k20, ValueDisplayed=2.2k
R66: library part CMP-0022710-2, "RES, 0.005, 1%, 0.25 W, AEC-Q200 Grade 1, 0603", Manufacturer=Panasonic, Power_W=250mW, TempCo=ppm/C, Tolerance_%=1%, Value2=0.25W, Value_Code=5L000, ValueDisplayed=0.005
R67: library part CMP-0023427-3, "RES, 120 k, 0.1%, 0.1 W, 0603", Manufacturer="Susumu Co Ltd", Power_W=100mW, Supplier Part Number 1=RG16P120KBCT-ND, TempCo="25 ppm/C", Tolerance_%=0.1%, Value2=0.1W, Value_Code=120k
R68: library part CMP-0026100-2, "RES, 1.00 M, 1%, 0.063 W, AEC-Q200 Grade 0, 0402", Manufacturer=Vishay-Dale, Power_W=63mW, Supplier Part Number 1=541-1.00MLCT-ND, TempCo="100 ppm/C", Tolerance_%=1%, Value2=0.063W, Value_Code=1M00, ValueDisplayed=1.00M
R69: library part CMP-0025921-5, "RES, 3.0 k, 5%, 0.1 W, 0603", Manufacturer=Yageo, Power_W=100mW, Supplier Part Number 1=311-3.0KGRCT-ND, TempCo="100 ppm/C", Tolerance_%=5%, Value2=0.1W, Value_Code=3k00, ValueDisplayed=3.0k
R72: library part CMP-0026003-3, "RES, 13.0 k, 1%, 0.063 W, AEC-Q200 Grade 0, 0402", Manufacturer=Vishay-Dale, Power_W=63mW, Supplier Part Number 1=541-13.0KLCT-ND, TempCo="100 ppm/C", Tolerance_%=1%, Value2=0.063W, Value_Code=13k0, ValueDisplayed=13.0k
R78 R81: library part CMP-0025932-5, "RES, 5.1 k, 5%, 0.1 W, 0603", Manufacturer=Yageo, Power_W=100mW, Supplier Part Number 1=311-5.1KGRCT-ND, TempCo="100 ppm/C", Tolerance_%=5%, Value2=0.1W, Value_Code=5k10, ValueDisplayed=5.1k
R79: library part CMP-0025975-3, "RES, 11.0 k, 1%, 0.063 W, AEC-Q200 Grade 0, 0402", Manufacturer=Vishay-Dale, Power_W=63mW, Supplier Part Number 1=541-11.0KLCT-ND, TempCo="100 ppm/C", Tolerance_%=1%, Value2=0.063W, Value_Code=11k0, ValueDisplayed=11.0k
R82: library part CMP-0026853-5, "RES, 1.1 k, 5%, 0.063 W, AEC-Q200 Grade 0, 0402", Manufacturer=Vishay-Dale, Power_W=63mW, Supplier Part Number 1=541-1.1KJCT-ND, TempCo="200 ppm/C", Tolerance_%=5%, Value2=0.063W, Value_Code=1k10, ValueDisplayed=1.1k
R85: library part CMP-0026414-2, "RES, 4.99 k, 1%, 0.063 W, AEC-Q200 Grade 0, 0402", Manufacturer=Vishay-Dale, Power_W=63mW, Supplier Part Number 1=541-4.99KLCT-ND, TempCo="100 ppm/C", Tolerance_%=1%, Value2=0.063W, Value_Code=4k99, ValueDisplayed=4.99k
R88 R89 R111 R112 R113 R127 R128 R129 R130 R133 R145 R146 R147 R161 R162 R163: library part CMP-0026237-2, "RES, 2.49 k, 1%, 0.063 W, AEC-Q200 Grade 0, 0402", Manufacturer=Vishay-Dale, Power_W=63mW, Supplier Part Number 1=541-2.49KLCT-ND, TempCo="100 ppm/C", Tolerance_%=1%, Value2=0.063W, Value_Code=2k49, ValueDisplayed=2.49k
R94: library part CMP-0026079-3, "RES, 1.21 k, 1%, 0.063 W, AEC-Q200 Grade 0, 0402", Manufacturer=Vishay-Dale, Power_W=63mW, Supplier Part Number 1=541-1.21KLCT-ND, TempCo="100 ppm/C", Tolerance_%=1%, Value2=0.063W, Value_Code=1k21, ValueDisplayed=1.21k
R107 R123 R124 R125 R151 R159 R160: library part CMP-0026231-2, "RES, 2.20 k, 1%, 0.063 W, AEC-Q200 Grade 0, 0402", Manufacturer=Vishay-Dale, Power_W=63mW, Supplier Part Number 1=541-2.20KLCT-ND, TempCo="100 ppm/C", Tolerance_%=1%, Value2=0.063W, Value_Code=2k20, ValueDisplayed=2.20k
R109 R143: library part CMP-0026515-2, "RES, 6.49 k, 1%, 0.063 W, AEC-Q200 Grade 0, 0402", Manufacturer=Vishay-Dale, Power_W=63mW, Supplier Part Number 1=541-6.49KLCT-ND, TempCo="100 ppm/C", Tolerance_%=1%, Value2=0.063W, Value_Code=6k49, ValueDisplayed=6.49k
R114 R115 R116 R117 R118 R119 R120 R121 R122 R126 R148 R149 R150 R152 R153 R154 R155 R156 R157 R158: library part CMP-0026299-2, "RES, 33.2, 1%, 0.063 W, AEC-Q200 Grade 0, 0402", Manufacturer=Vishay-Dale, Power_W=63mW, Supplier Part Number 1=541-33.2LCT-ND, TempCo="100 ppm/C", Tolerance_%=1%, Value2=0.063W, Value_Code=33R2, ValueDisplayed=33.2
R131 R134 R166 R168: library part CMP-0086542-2, "RMCF/RMCP Series General Purpose Thick Film Standard Power and High Power Chip Resistor", Manufacturer=Stackpole, TempCo=-
R132 R135 R167 R169: library part CMP-0025813-4, "RES, 470, 5%, 0.1 W, AEC-Q200 Grade 0, 0603", Manufacturer=Vishay-Dale, Power_W=100mW, Supplier Part Number 1=541-470GCT-ND, TempCo="200 ppm/C", Tolerance_%=5%, Value2=0.1W, Value_Code=470R, ValueDisplayed=470
R136 R170: library part CMP-0026757-1, "RES, 1.00 M, 1%, 0.063 W, AEC-Q200 Grade 0, 0402", Manufacturer="Stackpole Electronics Inc", Power_W=63mW, Supplier Part Number 1=RMCF0402FT1M00CT-ND, TempCo="100 ppm/C", Tolerance_%=1%, Value2=0.063W, Value_Code=1M00, ValueDisplayed=1.00M
R137: library part CMP-0026081-3, "RES, 1.27 k, 1%, 0.063 W, AEC-Q200 Grade 0, 0402", Manufacturer=Vishay-Dale, Power_W=63mW, Supplier Part Number 1=541-1.27KLCT-ND, TempCo="100 ppm/C", Tolerance_%=1%, Value2=0.063W, Value_Code=1k27, ValueDisplayed=1.27k
R139 R140: library part CMP-0026863-2, "RES, 1.5 M, 5%, 0.063 W, AEC-Q200 Grade 0, 0402", Manufacturer=Vishay-Dale, Power_W=63mW, Supplier Part Number 1=541-1.5MJCT-ND, TempCo="200 ppm/C", Tolerance_%=5%, Value2=0.063W, Value_Code=1M50, ValueDisplayed=1.5M
R164: library part CMP-0026824-3, "RES, 100, 5%, 0.063 W, AEC-Q200 Grade 0, 0402", Manufacturer=Vishay-Dale, Power_W=63mW, Supplier Part Number 1=541-100JCT-ND, TempCo="200 ppm/C", Tolerance_%=5%, Value2=0.063W, Value_Code=100R, ValueDisplayed=100
R172 R173: library part CMP-0026736-1, "RES, 470, 1%, 0.063 W, 0402", Manufacturer="Yageo America", Power_W=63mW, Supplier Part Number 1=311-470LRCT-ND, TempCo="100 ppm/C", Tolerance_%=1%, Value2=0.063W, Value_Code=470R, ValueDisplayed=470
R174 R175: library part CMP-0026825-5, "RES, 10 k, 5%, 0.063 W, AEC-Q200 Grade 0, 0402", Manufacturer=Vishay-Dale, Power_W=63mW, Supplier Part Number 1=541-10KJCT-ND, TempCo="200 ppm/C", Tolerance_%=5%, Value2=0.063W, Value_Code=10k0, ValueDisplayed=10k
R176: library part CMP-0026413-2, "RES, 4.87 k, 1%, 0.063 W, AEC-Q200 Grade 0, 0402", Manufacturer=Vishay-Dale, Power_W=63mW, Supplier Part Number 1=541-4.87KLCT-ND, TempCo="100 ppm/C", Tolerance_%=1%, Value2=0.063W, Value_Code=4k87, ValueDisplayed=4.87k
R177: library part CMP-0026946-3, "RES, 51, 5%, 0.063 W, AEC-Q200 Grade 0, 0402", Manufacturer=Vishay-Dale, Power_W=63mW, Supplier Part Number 1=541-51JCT-ND, TempCo="200 ppm/C", Tolerance_%=5%, Value2=0.063W, Value_Code=51R0, ValueDisplayed=51
RJ1 RJ2: library part CMP-0086350-1, "Connector, RJ45, 1x1, Gold, R/A, SMT", Manufacturer="Wurth Elektronik"
S1: library part CMP-0002328-1, "Switch, SPST, 0.05 A, 12 VDC, SMD", CurrentRating_mA=50A, Manufacturer=Diptronics
S2 S3 S5: library part CMP-0002233-1, "Switch, Dual SPDT,  2 Pos, 0.1A, 6VDC, SMD", CurrentRating_mA=100A, Manufacturer="Copal Electronics", Supplier Part Number 1=CASD20JCT-ND
S4: library part CMP-0002123-2, "SLIDE SWITCH DPDT  .1A, SMT", CurrentRating_mA=100A, Manufacturer="Copal Electronics", Supplier Part Number 1=CAS220JCT-ND
TP1 TP2 TP3 TP4 TP5 TP6 TP7 TP8: library part CMP-0078143-3, "TEST POINT.  No entry in BOM.", Manufacturer=N/A
U1: library part CMP-0097121-1, Manufacturer="Texas Instruments", Operating Temperature Range=to
U2: library part CMP-0077953-1, "MSP432E401YTPDT, PDT0128A (TQFP-128)", Alternate Manufacturer="Texas Instruments", Alternate PartNumber=MSP432E401YTPDTR
U3: library part CMP-0077709-1, "High-Precision Voltage Reference with Integrated High-Bandwidth Buffer, DGK0008A (VSSOP-8)", Alternate Manufacturer="Texas Instruments", Alternate PartNumber=REF6230IDGKT
U4 U5: library part CMP-0043115-3, "4-Channel ESD Protection Array for High-Speed Data Interfaces, DRY0006A (USON-6)", Breakdown Voltage(Min)(V)=6, IO Capacitance(Typ)(pF)=1.6, IO Leakage Current(nA)=1, Manufacturer="Texas Instruments", Operating Temperature Range="-40 to 85 C", Rating=Catalog
U6 U8 U9: library part CMP-0067418-1, "DUAL 10-Ohm SPDT ANALOG SWITCH, DGS0010A (VSSOP-10)", Alternate Manufacturer="Texas Instruments", Alternate PartNumber=TS5A23157DGST
U7: library part CMP-0051789-2, "Dual Buffer/Driver with Open-Drain Output, DBV0006A, LARGE T&R", F @ Nom Voltage(Max)(Mhz)=150, Generic Part Number=SN74LVC2G07, ICC @ Nom Voltage(Max)(mA)=0.01, Manufacturer="Texas Instruments", Operating Temperature Range(C)="-40 to 125", Rating=Catalog, tpd @ Nom Voltage(Max)(ns)=8.6,4.4,3.7,2.9, Voltage(Nom)(V)=1.8,2.5,3.3,5
U10: library part CMP-0081404-1, "Automotive High-Accuracy Window Supervisor With Reset Time Delay and Manual Reset, DSE0006A (WSON-6)", Alternate Manufacturer="Texas Instruments"
U11 U14: library part CMP-0089841-1, "3 Circuit IC Switch 2:1 75Ohm 16-TSSOP", Digikey Part Number=296-3833-1-ND, Manufacturer="Texas Instruments", Max Supply Voltage=5.5V, Min Supply Voltage=2V, Mouser Part Number=595-SN74LV4053APWR, Nominal Supply Current=20uA, On State Resistance=100-225Ω, Operating Temperature Range="-40°C to +85°C"
U12: library part CMP-0082059-1, "16 Kb I2C EEPROM Serial, SOIC-8", Manufacturer="ON Semiconductor", Supplier Part Number 1=CAT24C16WI-GT3CT-ND
U13: library part CMP-0066458-2, "8-Bit Dual-Supply Bus Transceiver with Configurable Voltage-Level Shifting and Three-State Outputs, PW0024A (TSSOP-24)", Alternate Manufacturer="Texas Instruments", Operating Temperature Range="-40 to 85 C", Rating=Catalog
U15: library part CMP-0080974-2, "3.3-V CAN Transceivers, D0008A (SOIC-8)", Alternate Manufacturer="Texas Instruments", Alternate PartNumber=TCAN332D
U16 U19 U21: library part CMP-0073613-3, "4-Channel Ultra-Low-Capacitance IEC ESD Protection Diode, DQA0010A (USON-10)", Alternate Manufacturer="Texas Instruments"
U17 U20: library part CMP-0860427-2, "DP83826ERHB, RHB0032M (VQFN-32)", Alternate Manufacturer="Texas Instruments"
U18: library part CMP-0051777-2, "Dual Inverter Buffer/Driver with Open-Drain Output, DBV0006A, LARGE T&R", F @ Nom Voltage(Max)(Mhz)=150, Generic Part Number=SN74LVC2G06, ICC @ Nom Voltage(Max)(mA)=0.01, Manufacturer="Texas Instruments", Operating Temperature Range(C)="-40 to 125,-40 to 85", Rating=Catalog, tpd @ Nom Voltage(Max)(ns)=8.2,4.4,3.9,3.4, Voltage(Nom)(V)=1.8,2.5,3.3,5
U22: library part CMP-0091799-1, "Linear Voltage Regulator IC Positive Adjustable 1 Output  1A 6-WSON (2x2)", Digikey Part Number=296-53048-1-ND, Dropout Voltage=161mV, Manufacturer="Texas Instruments", Max Supply Voltage=6V, Min Supply Voltage=1.5V, Mouser Part Number=595-TLV75901PDRVT, Nominal Supply Current=25uA, Operating Temperature Range="-40°C to +125°C", Output Voltage=0.55-5.5V
U23: library part CMP-0067212-2, "5V, 500mA, 4MHz Step-Up DC/DC Converter, YFF0006AEAE (DSBGA-6)", Alternate Manufacturer="Texas Instruments", Alternate PartNumber=TPS61241YFFT, Operating Temperature Range="-40 to 85 C", Rating=Catalog
U24: library part CMP-0093421-2, "1.5-A Low-Dropout Linear Regulator With Programmable Soft-Start", Dropout Voltage=150mV, Manufacturer="Texas Instruments", Max Supply Voltage=5.5V, Min Supply Voltage=800mV, Operating Temperature Range="-40°C to +125°C", Output Voltage=0.65-3.6V
U25: library part CMP-0091939-1, "Linear Voltage Regulator IC Positive Fixed 1 Output 300mA SOT-23-5", Digikey Part Number=296-47851-1-ND, Dropout Voltage=260mV, Manufacturer="Texas Instruments", Max Supply Voltage=5.5V, Min Supply Voltage=2V, Mouser Part Number=595-TLV70333DBVR, Nominal Supply Current=35-370uA, Operating Temperature Range="-40°C to +125°C", Output Voltage=3.3V
U26: library part CMP-0076064-3, "High-Speed, Low-Power, Robust EMC Quad-Channel Digital Isolator, DW0016B (SOIC-16)", Alternate Manufacturer="Texas Instruments", Alternate PartNumber=ISO7741DW, Operating Temperature Range="-55 to 125 C", Rating=Catalog
U27: library part CMP-0078446-2, "High Speed, Robust EMC Triple-Channel Digital Isolators, DW0016B (SOIC-16)", Alternate Manufacturer="Texas Instruments", Alternate PartNumber=ISO7731DW, Operating Temperature Range="-55 to 125 C", Rating=Catalog
USB1: library part CMP-0092137-1, "Connector, USB Type-C 24 pin Mid Mount dual row Receptacle Surface Mount", Manufacturer=MUP, Operating Temperature Range="-25°C to +85°C"
Y1: library part CMP-0004635-3, "Crystal, 16 MHz, 8pF, SMD", Frequency Stability=+/-30ppm, Frequency_Fixed=16MHz, Manufacturer=NDK, Supplier Part Number 1=644-1157-1-ND
Y2: library part CMP-0096024-2, "High-Performance BAW Oscillator", Frequency Stability=25ppm, Frequency_Fixed=25MHz, Load Capacitance=30pF, Manufacturer="Texas Instruments", Max Supply Current=50mA, Max Supply Voltage=3.465V, Min Supply Voltage=2.375V, Operating Temperature Range="-40°C to +105°C"
ZZ1: library part CMP-0077236-1
ZZ2: library part CMP-0077237-1
ZZ3: library part CMP-0077238-1

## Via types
v1: diameter 22, hole 8, Top Signal to Bottom Signal, tented both sides, 821 vias
v2: diameter 14, hole 8, Top Signal to Bottom Signal, tented both sides, 82 vias
v3: diameter 19.68, hole 7.87, Top Signal to Bottom Signal, tented top, 14 vias
v4: diameter 15.75, hole 7.87, Top Signal to Bottom Signal, tented both sides, 2 vias
v5: diameter 19.68, hole 7.87, Top Signal to Bottom Signal, 2 vias

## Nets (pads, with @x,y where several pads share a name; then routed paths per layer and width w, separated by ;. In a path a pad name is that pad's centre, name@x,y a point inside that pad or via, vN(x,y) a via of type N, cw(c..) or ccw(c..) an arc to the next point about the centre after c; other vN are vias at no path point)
25MHZ_CLK: B1.1 Y2.3 | length 130
  Top Signal w5: B1.1@1544.54,3345.91 1582.69,3345.91 1596.44,3332.16 Y2.3@1596.44,3259.71
+1V2_MCU: C59.1 C118.1 L1.1 R70.1 | length 244.6
  Bottom Signal w10: C59.1@956.99,4229.66 C59.1@953.16,4229.66 953.44,4229.37 v1(1010.34,4229.37) ; v1(987.09,4112.37) 987.09,4166.9 L1.1@993.17,4172.98 L1.1@993.17,4144.69 ; C118.1@1395.51,4915.88 1398.16,4913.23 v1(1398.16,4874.64) ; v1(1438.83,4874.64) 1438.83,4877.89 1445.02,4884.09 1445.02,4902.45 R70.1@1458.73,4916.15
